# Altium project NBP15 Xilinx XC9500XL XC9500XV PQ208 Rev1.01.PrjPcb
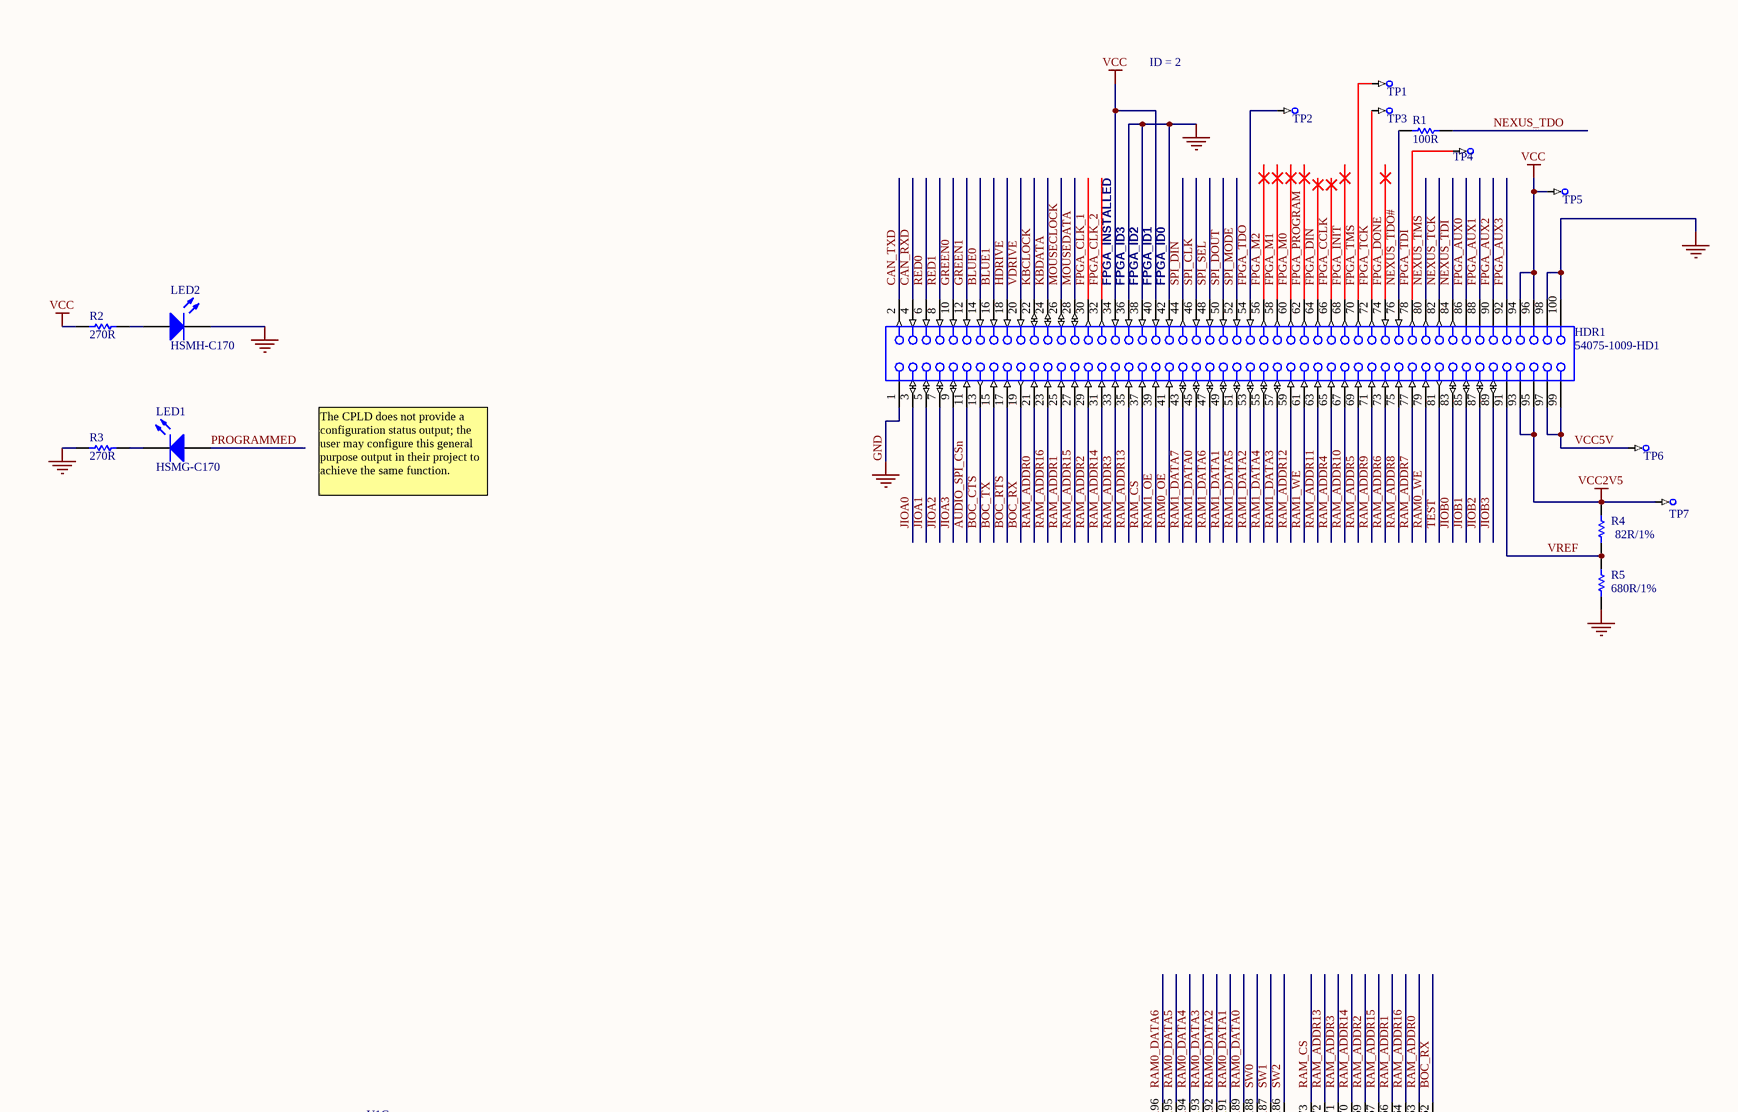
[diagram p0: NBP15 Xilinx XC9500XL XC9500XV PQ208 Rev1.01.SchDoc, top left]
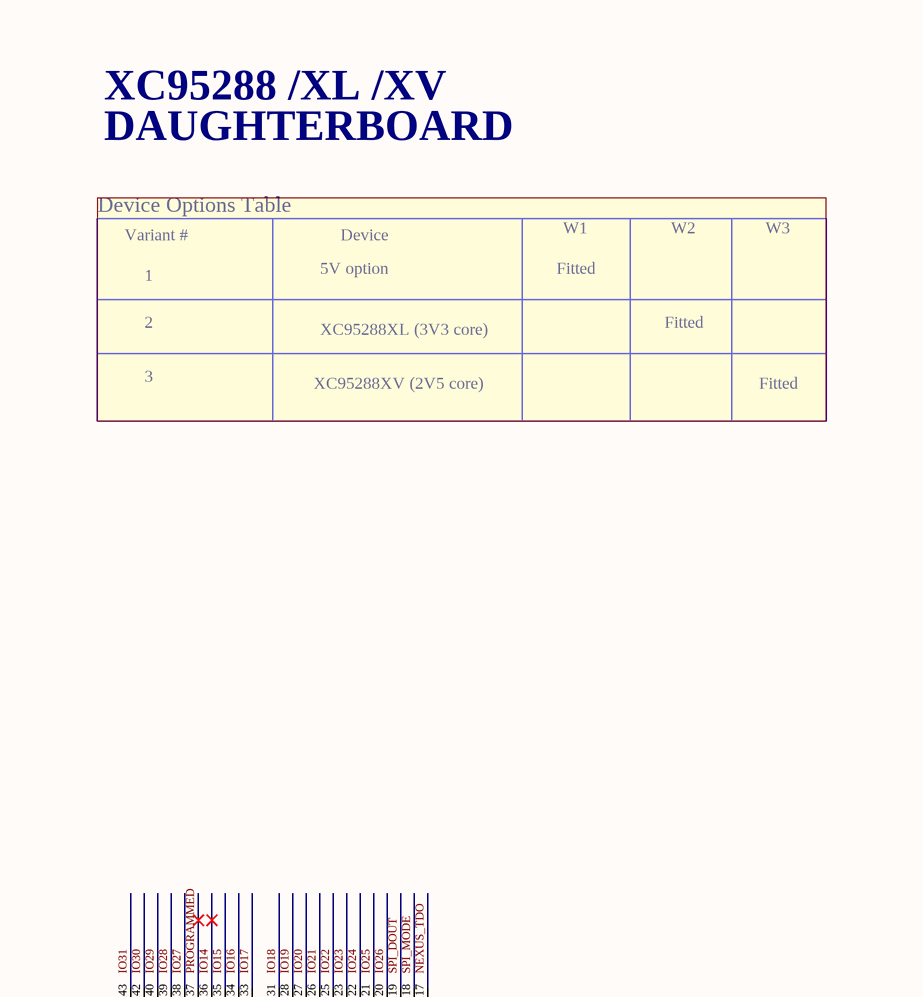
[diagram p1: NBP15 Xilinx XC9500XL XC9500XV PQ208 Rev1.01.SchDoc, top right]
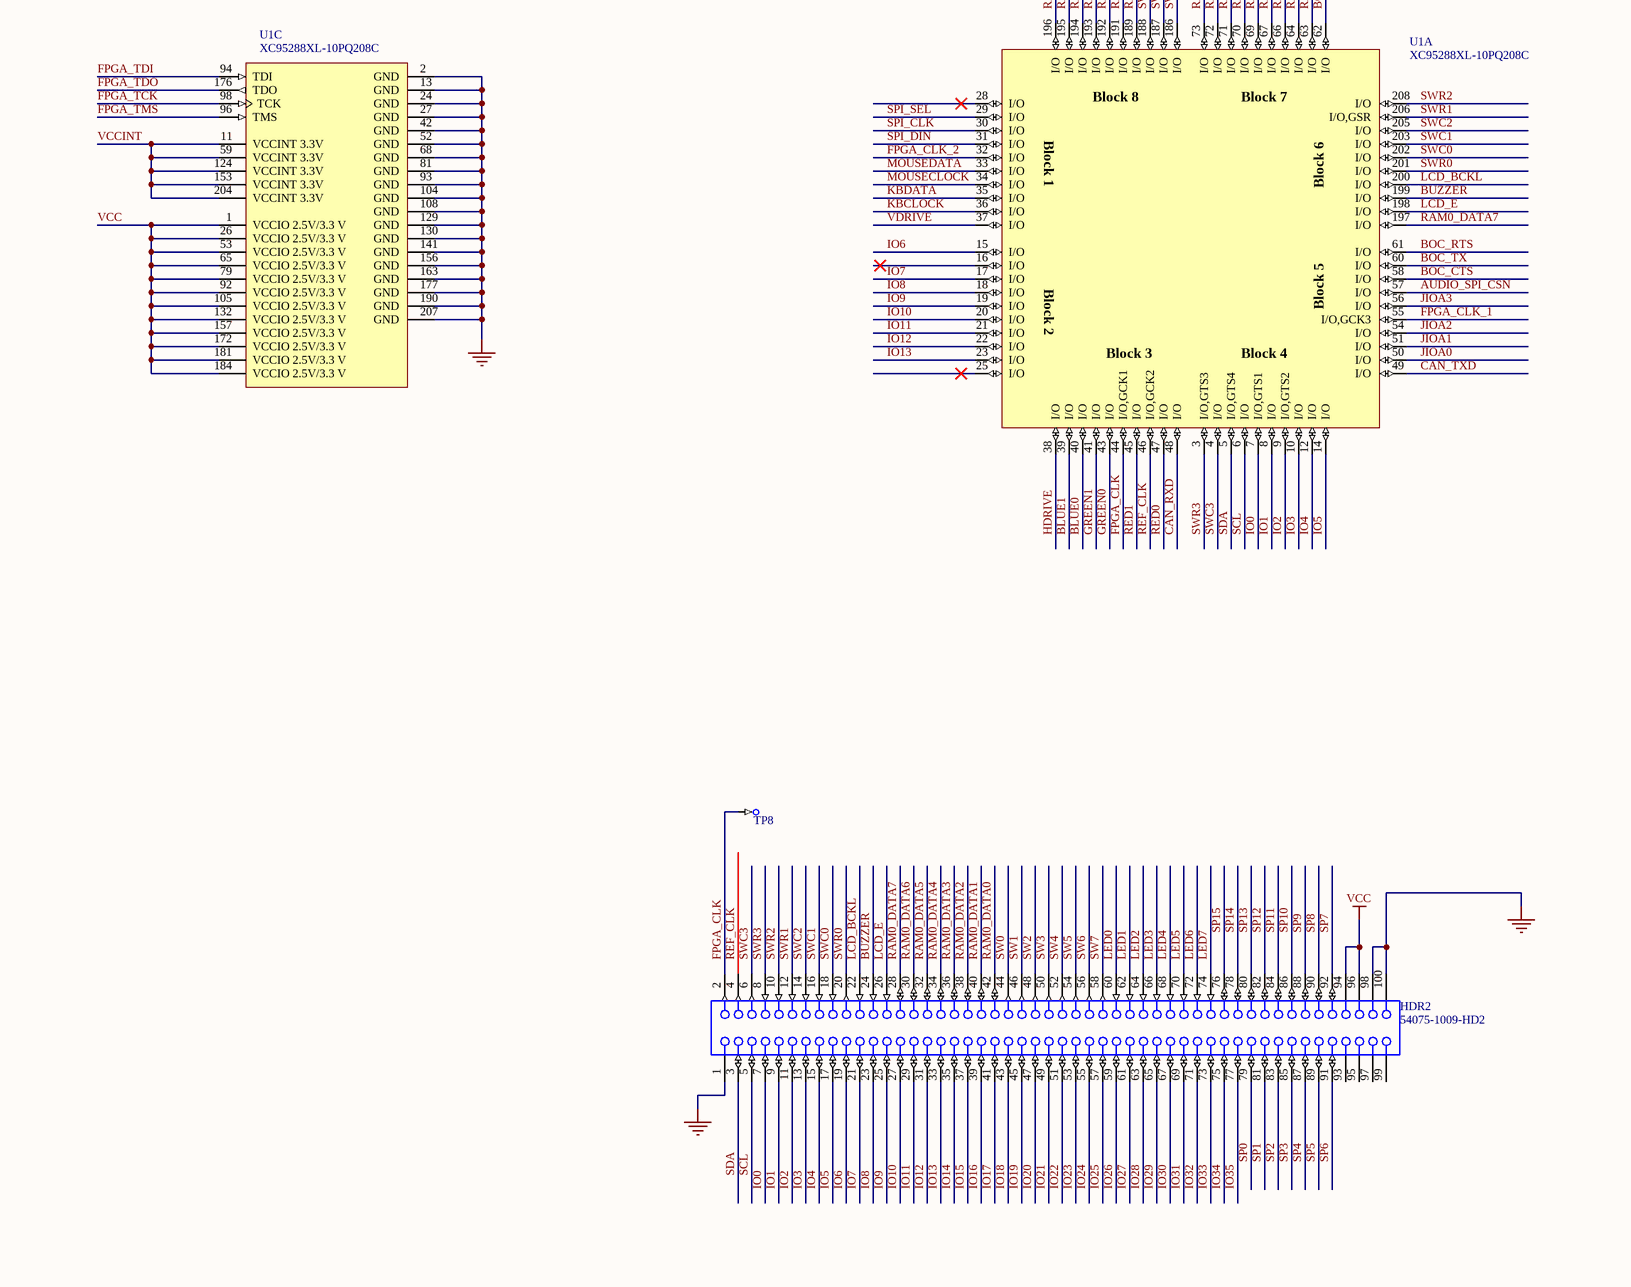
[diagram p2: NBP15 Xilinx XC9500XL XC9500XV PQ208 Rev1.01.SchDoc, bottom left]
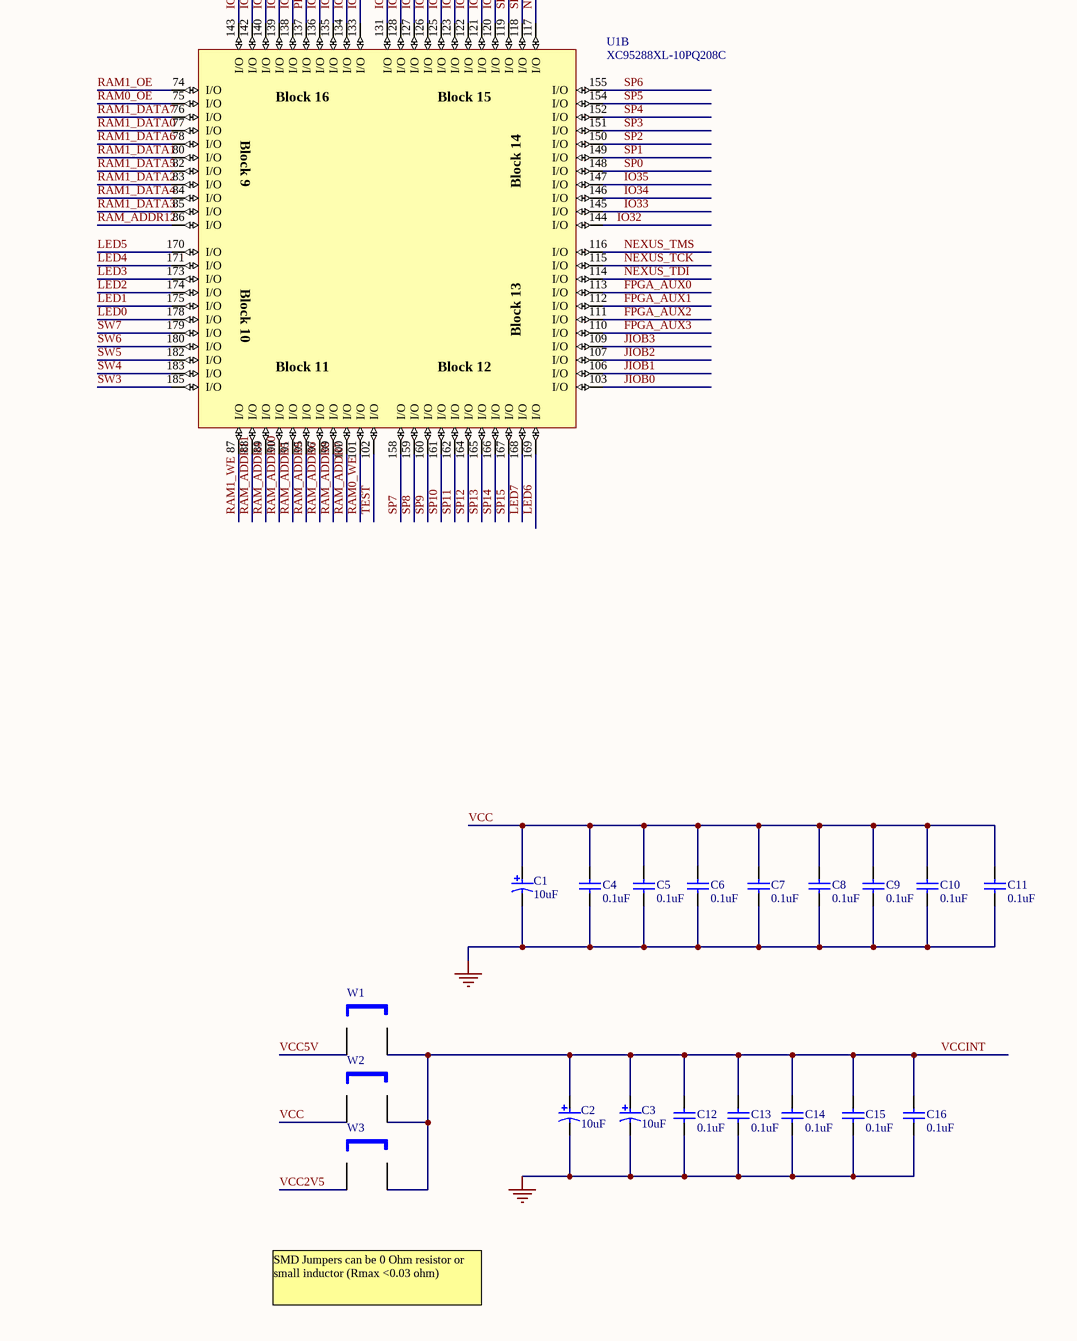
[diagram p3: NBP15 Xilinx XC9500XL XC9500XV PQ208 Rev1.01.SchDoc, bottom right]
1 sheet, 37 parts. Net scope: global (net labels, ports and power ports of the same name join across sheets).
Board file: NBP15 Xilinx XC9500XL XC9500XV PQ208 Rev1.01.PcbDoc

## Sheet NBP15 Xilinx XC9500XL XC9500XV PQ208 Rev1.01.SchDoc: Xilinx XC95288 Daughterboard
size A1; Organization: Protel International P/L; Address1: L3, 12a Rodborough Rd; Address2: Frenchs Forest; Address3: NSW; Address4: Australia 2086; DocumentNumber: 1; Revision: 1.01; SheetNumber: 1; SheetTotal: 1

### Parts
C1  10uF  [MCCT-B]
C2  10uF  [MCCT-B]
C3  10uF  [MCCT-B]
C4  0.1uF  [CC2012-0805]
C5  0.1uF  [CC2012-0805]
C6  0.1uF  [CC2012-0805]
C7  0.1uF  [CC2012-0805]
C8  0.1uF  [CC2012-0805]
C9  0.1uF  [CC2012-0805]
C10  0.1uF  [CC2012-0805]
C11  0.1uF  [CC2012-0805]
C12  0.1uF  [CC2012-0805]
C13  0.1uF  [CC2012-0805]
C14  0.1uF  [CC2012-0805]
C15  0.1uF  [CC2012-0805]
C16  0.1uF  [CC2012-0805]
HDR1  54075-1009-HD1  [54075]
HDR2  54075-1009-HD2  [54075]
LED1  HSMG-C170  [SMD _LED]
LED2  HSMH-C170  [SMD _LED]
R1  100R  [CC2012-0805]
R2  270R  [CC2012-0805]
R3  270R  [CC2012-0805]
R4  82R/1%  [CC2012-0805]
R5  680R/1%  [CC2012-0805]
TP1  TestPin  [TestPin]  (value not drawn)  (no BOM)
TP2  TestPin  [TestPin]  (value not drawn)  (no BOM)
TP3  TestPin  [TestPin]  (value not drawn)  (no BOM)
TP4  TestPin  [TestPin]  (value not drawn)  (no BOM)
TP5  TestPin  [TestPin]  (value not drawn)  (no BOM)
TP6  TestPin  [TestPin]  (value not drawn)  (no BOM)
TP7  TestPin  [TestPin]  (value not drawn)  (no BOM)
TP8  TestPin  [TestPin]  (value not drawn)  (no BOM)
U1  XC95288XL-10PQ208C  [PQ208]  (parts A,B,C of 3)
W1  Jumper  [CC2012-0805]  (value not drawn)
W2  Jumper  [CC2012-0805]  (value not drawn)
W3  Jumper  [CC2012-0805]  (value not drawn)

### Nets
GND: C1.2 C2.2 C3.2 C4.2 C5.2 C6.2 C7.2 C8.2 C9.2 C10.2 C11.2 C12.2 C13.2 C14.2 C15.2 C16.2 HDR1.1 HDR1.36 HDR1.38 HDR1.42 HDR1.98 HDR1.100 HDR2.1 HDR2.98 HDR2.100 LED2.2(K) R3.1 R5.2 U1.2(GND) U1.13(GND) U1.24(GND) U1.27(GND) U1.42(GND) U1.52(GND) U1.68(GND) U1.81(GND) U1.93(GND) U1.104(GND) U1.108(GND) U1.129(GND) U1.130(GND) U1.141(GND) U1.156(GND) U1.163(GND) U1.177(GND) U1.190(GND) U1.207(GND)
VCC: C1.1 C4.1 C5.1 C6.1 C7.1 C8.1 C9.1 C10.1 C11.1 HDR1.34 HDR1.40 HDR1.94 HDR1.96 HDR2.94 HDR2.96 R2.1 TP5.1 U1.1(VCCIO_2.5V/3.3_V) U1.26(VCCIO_2.5V/3.3_V) U1.53(VCCIO_2.5V/3.3_V) U1.65(VCCIO_2.5V/3.3_V) U1.79(VCCIO_2.5V/3.3_V) U1.92(VCCIO_2.5V/3.3_V) U1.105(VCCIO_2.5V/3.3_V) U1.132(VCCIO_2.5V/3.3_V) U1.157(VCCIO_2.5V/3.3_V) U1.172(VCCIO_2.5V/3.3_V) U1.181(VCCIO_2.5V/3.3_V) U1.184(VCCIO_2.5V/3.3_V) W2.1
VCC2V5: HDR1.93 HDR1.95 R4.1 TP7.1 W3.1
AUDIO_SPI_CSn: HDR1.11 U1.57(I/O)
BLUE0: HDR1.14 U1.40(I/O)
BLUE1: HDR1.16 U1.39(I/O)
BOC_CTS: HDR1.13 U1.58(I/O)
BOC_RTS: HDR1.17 U1.61(I/O)
BOC_RX: HDR1.19 U1.62(I/O)
BOC_TX: HDR1.15 U1.60(I/O)
BUZZER: HDR2.24 U1.199(I/O)
CAN_RXD: HDR1.4 U1.48(I/O)
CAN_TXD: HDR1.2 U1.49(I/O)
FPGA_AUX0: HDR1.86 U1.113(I/O)
FPGA_AUX1: HDR1.88 U1.112(I/O)
FPGA_AUX2: HDR1.90 U1.111(I/O)
FPGA_AUX3: HDR1.92 U1.110(I/O)
FPGA_CCLK: HDR1.66
FPGA_CLK: HDR2.2 TP8.1 U1.44(I/O,GCK1)
FPGA_CLK_1: HDR1.30 U1.55(I/O,GCK3)
FPGA_CLK_2: HDR1.32 U1.32(I/O)
FPGA_DIN: HDR1.64
FPGA_DONE: HDR1.74
FPGA_INIT: HDR1.68
FPGA_M0: HDR1.60
FPGA_M1: HDR1.58
FPGA_M2: HDR1.56
FPGA_PROGRAM: HDR1.62
FPGA_TCK: HDR1.72 TP3.1 U1.98(TCK)
FPGA_TDI: HDR1.78 TP4.1 U1.94(TDI)
FPGA_TDO: HDR1.54 TP2.1 U1.176(TDO)
FPGA_TMS: HDR1.70 TP1.1 U1.96(TMS)
GREEN0: HDR1.10 U1.43(I/O)
GREEN1: HDR1.12 U1.41(I/O)
HDRIVE: HDR1.18 U1.38(I/O)
IO0: HDR2.7 U1.7(I/O,GTS1)
IO1: HDR2.9 U1.8(I/O)
IO2: HDR2.11 U1.9(I/O,GTS2)
IO3: HDR2.13 U1.10(I/O)
IO4: HDR2.15 U1.12(I/O)
IO5: HDR2.17 U1.14(I/O)
IO6: HDR2.19 U1.15(I/O)
IO7: HDR2.21 U1.17(I/O)
IO8: HDR2.23 U1.18(I/O)
IO9: HDR2.25 U1.19(I/O)
IO10: HDR2.27 U1.20(I/O)
IO11: HDR2.29 U1.21(I/O)
IO12: HDR2.31 U1.22(I/O)
IO13: HDR2.33 U1.23(I/O)
IO14: HDR2.35 U1.136(I/O)
IO15: HDR2.37 U1.135(I/O)
IO16: HDR2.39 U1.134(I/O)
IO17: HDR2.41 U1.133(I/O)
IO18: HDR2.43 U1.131(I/O)
IO19: HDR2.45 U1.128(I/O)
IO20: HDR2.47 U1.127(I/O)
IO21: HDR2.49 U1.126(I/O)
IO22: HDR2.51 U1.125(I/O)
IO23: HDR2.53 U1.123(I/O)
IO24: HDR2.55 U1.122(I/O)
IO25: HDR2.57 U1.121(I/O)
IO26: HDR2.59 U1.120(I/O)
IO27: HDR2.61 U1.138(I/O)
IO28: HDR2.63 U1.139(I/O)
IO29: HDR2.65 U1.140(I/O)
IO30: HDR2.67 U1.142(I/O)
IO31: HDR2.69 U1.143(I/O)
IO32: HDR2.71 U1.144(I/O)
IO33: HDR2.73 U1.145(I/O)
IO34: HDR2.75 U1.146(I/O)
IO35: HDR2.77 U1.147(I/O)
JIOA0: HDR1.3 U1.50(I/O)
JIOA1: HDR1.5 U1.51(I/O)
JIOA2: HDR1.7 U1.54(I/O)
JIOA3: HDR1.9 U1.56(I/O)
JIOB0: HDR1.83 U1.103(I/O)
JIOB1: HDR1.85 U1.106(I/O)
JIOB2: HDR1.87 U1.107(I/O)
JIOB3: HDR1.89 U1.109(I/O)
KBCLOCK: HDR1.22 U1.36(I/O)
KBDATA: HDR1.24 U1.35(I/O)
LCD_BCKL: HDR2.22 U1.200(I/O)
LCD_E: HDR2.26 U1.198(I/O)
LED0: HDR2.60 U1.178(I/O)
LED1: HDR2.62 U1.175(I/O)
LED2: HDR2.64 U1.174(I/O)
LED3: HDR2.66 U1.173(I/O)
LED4: HDR2.68 U1.171(I/O)
LED5: HDR2.70 U1.170(I/O)
LED6: HDR2.72 U1.169(I/O)
LED7: HDR2.74 U1.168(I/O)
MOUSECLOCK: HDR1.26 U1.34(I/O)
MOUSEDATA: HDR1.28 U1.33(I/O)
NEXUS_TCK: HDR1.82 U1.115(I/O)
NEXUS_TDI: HDR1.84 U1.114(I/O)
NEXUS_TDO: R1.2 U1.117(I/O)
NEXUS_TDO#: HDR1.76 R1.1
NEXUS_TMS: HDR1.80 U1.116(I/O)
PROGRAMMED: LED1.1(A) U1.137(I/O)
RAM0_DATA0: HDR2.42 U1.189(I/O)
RAM0_DATA1: HDR2.40 U1.191(I/O)
RAM0_DATA2: HDR2.38 U1.192(I/O)
RAM0_DATA3: HDR2.36 U1.193(I/O)
RAM0_DATA4: HDR2.34 U1.194(I/O)
RAM0_DATA5: HDR2.32 U1.195(I/O)
RAM0_DATA6: HDR2.30 U1.196(I/O)
RAM0_DATA7: HDR2.28 U1.197(I/O)
RAM0_OE: HDR1.41 U1.75(I/O)
RAM0_WE: HDR1.79 U1.101(I/O)
RAM1_DATA0: HDR1.45 U1.77(I/O)
RAM1_DATA1: HDR1.49 U1.80(I/O)
RAM1_DATA2: HDR1.53 U1.83(I/O)
RAM1_DATA3: HDR1.57 U1.85(I/O)
RAM1_DATA4: HDR1.55 U1.84(I/O)
RAM1_DATA5: HDR1.51 U1.82(I/O)
RAM1_DATA6: HDR1.47 U1.78(I/O)
RAM1_DATA7: HDR1.43 U1.76(I/O)
RAM1_OE: HDR1.39 U1.74(I/O)
RAM1_WE: HDR1.61 U1.87(I/O)
RAM_ADDR0: HDR1.21 U1.63(I/O)
RAM_ADDR1: HDR1.25 U1.66(I/O)
RAM_ADDR2: HDR1.29 U1.69(I/O)
RAM_ADDR3: HDR1.33 U1.71(I/O)
RAM_ADDR4: HDR1.65 U1.89(I/O)
RAM_ADDR5: HDR1.69 U1.91(I/O)
RAM_ADDR6: HDR1.73 U1.97(I/O)
RAM_ADDR7: HDR1.77 U1.100(I/O)
RAM_ADDR8: HDR1.75 U1.99(I/O)
RAM_ADDR9: HDR1.71 U1.95(I/O)
RAM_ADDR10: HDR1.67 U1.90(I/O)
RAM_ADDR11: HDR1.63 U1.88(I/O)
RAM_ADDR12: HDR1.59 U1.86(I/O)
RAM_ADDR13: HDR1.35 U1.72(I/O)
RAM_ADDR14: HDR1.31 U1.70(I/O)
RAM_ADDR15: HDR1.27 U1.67(I/O)
RAM_ADDR16: HDR1.23 U1.64(I/O)
RAM_CS: HDR1.37 U1.73(I/O)
RED0: HDR1.6 U1.47(I/O)
RED1: HDR1.8 U1.45(I/O)
REF_CLK: HDR2.4 U1.46(I/O,GCK2)
SCL: HDR2.5 U1.6(I/O)
SDA: HDR2.3 U1.5(I/O,GTS4)
SP0: HDR2.79 U1.148(I/O)
SP1: HDR2.81 U1.149(I/O)
SP2: HDR2.83 U1.150(I/O)
SP3: HDR2.85 U1.151(I/O)
SP4: HDR2.87 U1.152(I/O)
SP5: HDR2.89 U1.154(I/O)
SP6: HDR2.91 U1.155(I/O)
SP7: HDR2.92 U1.158(I/O)
SP8: HDR2.90 U1.159(I/O)
SP9: HDR2.88 U1.160(I/O)
SP10: HDR2.86 U1.161(I/O)
SP11: HDR2.84 U1.162(I/O)
SP12: HDR2.82 U1.164(I/O)
SP13: HDR2.80 U1.165(I/O)
SP14: HDR2.78 U1.166(I/O)
SP15: HDR2.76 U1.167(I/O)
SPI_CLK: HDR1.46 U1.30(I/O)
SPI_DIN: HDR1.44 U1.31(I/O)
SPI_DOUT: HDR1.50 U1.119(I/O)
SPI_MODE: HDR1.52 U1.118(I/O)
SPI_SEL: HDR1.48 U1.29(I/O)
SW0: HDR2.44 U1.188(I/O)
SW1: HDR2.46 U1.187(I/O)
SW2: HDR2.48 U1.186(I/O)
SW3: HDR2.50 U1.185(I/O)
SW4: HDR2.52 U1.183(I/O)
SW5: HDR2.54 U1.182(I/O)
SW6: HDR2.56 U1.180(I/O)
SW7: HDR2.58 U1.179(I/O)
SWC0: HDR2.18 U1.202(I/O)
SWC1: HDR2.16 U1.203(I/O)
SWC2: HDR2.14 U1.205(I/O)
SWC3: HDR2.6 U1.4(I/O)
SWR0: HDR2.20 U1.201(I/O)
SWR1: HDR2.12 U1.206(I/O,GSR)
SWR2: HDR2.10 U1.208(I/O)
SWR3: HDR2.8 U1.3(I/O,GTS3)
TEST: HDR1.81 U1.102(I/O)
VCC5V: HDR1.97 HDR1.99 TP6.1 W1.1
VCCINT: C2.1 C3.1 C12.1 C13.1 C14.1 C15.1 C16.1 U1.11(VCCINT_3.3V) U1.59(VCCINT_3.3V) U1.124(VCCINT_3.3V) U1.153(VCCINT_3.3V) U1.204(VCCINT_3.3V) W1.2 W2.2 W3.2
VDRIVE: HDR1.20 U1.37(I/O)
VREF: HDR1.91 R4.2 R5.1
NetLED1_2: LED1.2(K) R3.2
NetLED2_1: LED2.1(A) R2.2

Not connected (* = marked no-connect by the designer): HDR2 93 95 97 99; U1 16(I/O)* 25(I/O)* 28(I/O)*

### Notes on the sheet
- ID = 2
- XC95288 /XL /XV
- (near HDR1) FPGA_INSTALLED
- (near HDR1) FPGA_ID3
- (near HDR1) FPGA_ID2
- (near HDR1) FPGA_ID1
- (near HDR1) FPGA_ID0
- DAUGHTERBOARD
- Device Options Table
- Variant #
- Device
- W1
- W2
- W3
- 1
- 2
- 5V option
- Fitted
- The CPLD does not provide a configuration status output; the user may configure this general purpose output in their project to achieve the same function.
- 3
- XC95288XV (2V5 core)
- XC95288XL (3V3 core)
- SMD Jumpers can be 0 Ohm resistor or small inductor (Rmax <0.03 ohm)

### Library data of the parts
C1-C3 = CAP_POLAR: Polar Capacitor
C4-C16 = CAP: Capacitor
HDR1 = 54075-1009-HD1: Board-to-Board, Docking Station, 0.80mm (.031") Pitch, Shielded Receptacle, Vertical, Ultra Low Profile, SMT; Manufacturer: Molex; Package Information: Latest Revision: Jun-2001; Mating Height: 8.5mm; Voltage: 100V; Current: 0.5A; Contact Resistance: 40mOhm max; PCB Layout: Complies with Manufacturer's Recommendation.
HDR2 = 54075-1009-HD2: Board-to-Board, Docking Station, 0.80mm (.031") Pitch, Shielded Receptacle, Vertical, Ultra Low Profile, SMT; Manufacturer: Molex; Package Information: Latest Revision: Jun-2001; Mating Height: 8.5mm; Voltage: 100V; Current: 0.5A; Contact Resistance: 40mOhm max; PCB Layout: Complies with Manufacturer's Recommendation.
LED1 LED2 = HSMX-C670: Typical RED GaAs SMD LED Agilent make; Manufacturer: Generic Components; Class I: Optoelectronic; Fitted: True
R1-R5 = RES: Resistor
U1 = XC95288XL-10PQ208C: FastFLASH XC95288XL High Performance CPLD with 288 Macrocells, 208-Pin PQFP, Commercial Grade; Package Information: Latest Revision: ver1.1, Oct-2002; Code - JEDEC: MS-029-FA-1
W1-W3 = Jumper: Jumper Wire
